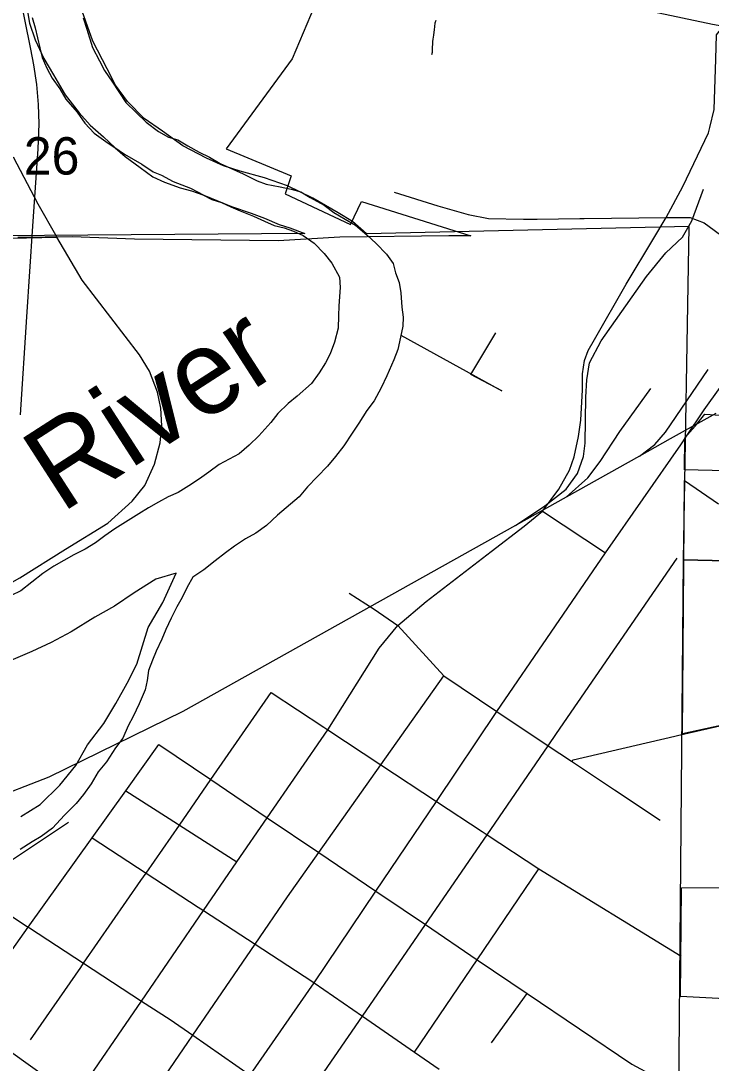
# Model space of a CAD drawing. Extents: x -8.5 to 18.7, y -20.3 to 7.
# Drawn here: x -4.269 to -2.724, y 1.955 to 4.29 of the extents above; entities that cross this region are included whole.
import ezdxf

# ---------------------------------------------------------------- set-up
doc = ezdxf.new("R2010")
doc.units = 0
for name, color, linetype in [('GM_X_City_Street', 7, 'Continuous'), ('GM_X_County_Road', 7, 'Continuous'), ('GM_X_Major_River', 7, 'Continuous'), ('GM_X_Major_River_Text', 7, 'Continuous'), ('GM_X_Minor_River', 7, 'Continuous'), ('GM_X_Rail_Line', 7, 'Continuous'), ('GM_X_Section', 7, 'Continuous'), ('GM_X_Section_Text', 7, 'Continuous'), ('GM_X_Township_Road', 7, 'Continuous')]:
    doc.layers.add(name, color=color, linetype=linetype)

msp = doc.modelspace()

# ---------------------------------------------------------------- linework, layer by layer
at = {"layer": 'GM_X_City_Street'}
for p, q in [((-3.1135, 3.8456), (-3.0178, 3.8468)), ((-3.1012, 3.1917), (-2.9599, 3.0981)), ((-4.0345, 2.5653), (-3.9182, 2.4909)), ((-3.2152, 2.0004), (-3.1355, 2.111))]:
    msp.add_line(p, q, dxfattribs=at)
for points in [[(-3.5552, 4.4573), (-3.6617, 4.2047), (-3.8097, 4.0028), (-3.6637, 3.9428), (-3.6775, 3.9025), (-3.5312, 3.8333), (-3.5068, 3.8847), (-3.2619, 3.8083), (-3.3107, 3.8078), (-3.5552, 3.8048), (-3.6928, 3.7972), (-4.0146, 3.8004), (-4.1541, 3.8061), (-4.2764, 3.8042)], [(-2.2079, 4.2918), (-2.2137, 4.1138), (-2.3043, 4.1716), (-2.4194, 4.2152), (-2.5061, 4.2422), (-2.6097, 4.2619), (-2.7206, 4.2815), (-3.5022, 4.4472)], [(-3.4331, 3.9059), (-3.3358, 3.8751), (-3.2679, 3.8558), (-3.2219, 3.8466), (-3.1441, 3.8452), (-3.1135, 3.8456)], [(-3.4249, 2.9356), (-3.3618, 2.9894), (-3.2164, 3.1009), (-3.142, 3.1578), (-3.1012, 3.1917), (-3.0649, 3.2408), (-3.0409, 3.2833), (-3.0302, 3.3131), (-3.021, 3.3584), (-3.0155, 3.3954), (-3.0114, 3.4633), (-3.0114, 3.4993), (-3.0076, 3.5292), (-2.999, 3.5514), (-2.985, 3.5761), (-2.914, 3.6995), (-2.8523, 3.803), (-2.8242, 3.8493)], [(-3.0178, 3.8468), (-3.0083, 3.8469), (-2.8242, 3.8493)], [(-2.8242, 3.8493), (-2.771, 3.8493), (-2.7391, 3.8373), (-2.5845, 3.7238)], [(-4.855, 2.6195), (-4.7618, 2.6604), (-4.7141, 2.6911), (-4.6291, 2.7728), (-4.4997, 2.9022), (-4.3942, 2.9737), (-4.2717, 3.0418), (-4.1696, 3.1065), (-4.0744, 3.1643), (-4.0203, 3.2136), (-3.9919, 3.249), (-3.9698, 3.2969), (-3.9571, 3.3442), (-3.9535, 3.3827), (-3.9557, 3.4219), (-3.9632, 3.458), (-3.9812, 3.5046), (-4.0037, 3.5412), (-4.1324, 3.709), (-4.189, 3.8052)], [(-2.5677, 3.2786), (-2.7832, 3.2842), (-2.7825, 3.3554), (-2.7596, 3.3817), (-2.7381, 3.4083), (-2.7026, 3.4067)], [(-2.7021, 2.7117), (-2.7882, 2.6929), (-2.7834, 3.2602), (-2.7075, 3.208)], [(-3.6846, 1.7981), (-3.6473, 1.8524), (-3.5983, 1.9238), (-3.5046, 2.0602), (-3.3636, 2.2654), (-3.2254, 2.4668), (-3.0885, 2.666), (-3.0696, 2.6935), (-2.7999, 3.0863)], [(-3.5343, 3.0076), (-3.4784, 2.9719), (-3.4249, 2.9356)], [(-4.0651, 1.7538), (-3.8957, 2.0013), (-3.8846, 2.0175), (-3.7449, 2.2214), (-3.672, 2.3279), (-3.6021, 2.4267), (-3.4631, 2.6233), (-3.3221, 2.8227)], [(-4.2474, 2.0074), (-4.1352, 2.1694), (-4.1287, 2.179), (-4.0006, 2.3639), (-3.9889, 2.3809), (-3.9144, 2.4884), (-3.844, 2.5902), (-3.7089, 2.7853)], [(-3.7089, 2.7853), (-3.5908, 2.7075), (-3.5823, 2.7018), (-3.4631, 2.6233), (-3.3389, 2.5415), (-3.2364, 2.474)], [(-4.4625, 1.9578), (-4.3961, 2.055), (-4.3292, 2.1531), (-4.2528, 2.26), (-4.1098, 2.4599), (-4.0345, 2.5653), (-3.9604, 2.6689)], [(-3.9604, 2.6689), (-3.844, 2.5902), (-3.7175, 2.5047), (-3.6021, 2.4267), (-3.4745, 2.3404), (-3.4132, 2.299), (-3.3636, 2.2654), (-3.2476, 2.1868), (-3.1355, 2.111), (-2.9015, 1.9525), (-2.8514, 1.926), (-2.7975, 1.8934), (-2.779, 1.8934), (-2.7151, 1.9279)], [(-3.0367, 2.6314), (-2.9401, 2.5673), (-2.8378, 2.4994)], [(-4.3286, 2.3757), (-4.308, 2.398), (-4.1625, 2.495)], [(-3.9182, 2.4909), (-3.9144, 2.4884), (-3.7854, 2.4058)], [(-4.1098, 2.4599), (-3.9889, 2.3809), (-3.8724, 2.3048), (-3.8601, 2.2968), (-3.7449, 2.2214), (-3.618, 2.1385), (-3.6129, 2.1352)], [(-3.2364, 2.474), (-3.2254, 2.4668), (-3.1098, 2.3907), (-2.791, 2.195)], [(-3.3878, 1.9794), (-3.2476, 2.1868), (-3.1098, 2.3907)], [(-4.3667, 2.3345), (-4.2528, 2.26), (-4.2496, 2.258)], [(-2.2535, 2.0761), (-2.7923, 2.1042), (-2.79, 2.3481), (-2.595, 2.3486)], [(-4.2496, 2.258), (-4.1287, 2.179), (-3.999, 2.0943), (-3.9351, 2.0526), (-3.8846, 2.0175), (-3.756, 1.928), (-3.6473, 1.8524), (-3.6362, 1.8446), (-3.5475, 1.7829), (-3.4907, 1.7508), (-3.4206, 1.7225), (-3.4109, 1.7186), (-3.2809, 1.6661), (-3.1664, 1.6197), (-3.0423, 1.5696), (-2.9414, 1.5288), (-2.937, 1.5266), (-2.8785, 1.4971), (-2.7977, 1.4775)], [(-4.6059, 2.2049), (-4.5241, 2.1464), (-4.5198, 2.1433), (-4.3961, 2.055), (-4.3932, 2.0529), (-4.1477, 1.8776)]]:
    msp.add_lwpolyline(points, dxfattribs=at)
at = {"layer": 'GM_X_County_Road'}
msp.add_line((-2.7773, 3.3618), (-2.7436, 3.4117), dxfattribs=at)
for points in [[(-2.8242, 3.8493), (-2.7874, 3.9185), (-2.7297, 4.0387), (-2.7267, 4.0507), (-2.7167, 4.0909), (-2.7135, 4.2041), (-2.7119, 4.2584), (-2.6997, 4.2732)], [(-2.7436, 3.4117), (-2.7391, 3.4184), (-2.7036, 3.4685), (-2.6743, 3.5046), (-2.6518, 3.5266), (-2.6057, 3.5626), (-2.5098, 3.6339)], [(-3.2033, 2.7427), (-2.9599, 3.0981), (-2.7919, 3.3402), (-2.7773, 3.3618)], [(-4.2006, 1.7945), (-4.197, 1.8032), (-4.1944, 1.8094), (-4.1477, 1.8776), (-3.999, 2.0943), (-3.8601, 2.2968), (-3.7854, 2.4058), (-3.7175, 2.5047), (-3.5823, 2.7018), (-3.4667, 2.8848), (-3.4249, 2.9356)], [(-3.4249, 2.9356), (-3.3221, 2.8227), (-3.2033, 2.7427)], [(-3.7548, 1.9296), (-3.6129, 2.1352), (-3.4745, 2.3404), (-3.3389, 2.5415), (-3.2033, 2.7427)], [(-3.2033, 2.7427), (-3.0885, 2.666), (-3.0367, 2.6314), (-3.0345, 2.6328)], [(-2.7988, 2.6888), (-2.688, 2.7147), (-2.6802, 2.7165)], [(-3.0345, 2.6328), (-3.0324, 2.6342), (-2.8047, 2.6874), (-2.7988, 2.6888)], [(-3.6129, 2.1352), (-3.5046, 2.0602), (-3.3878, 1.9794), (-3.333, 1.9415)]]:
    msp.add_lwpolyline(points, dxfattribs=at)
at = {"layer": 'GM_X_Major_River'}
for points in [[(-4.2438, 4.2971), (-4.2372, 4.2742), (-4.2322, 4.2514), (-4.2271, 4.2293), (-4.2213, 4.2073), (-4.2109, 4.1836), (-4.1991, 4.1615), (-4.1819, 4.137), (-4.1685, 4.1141), (-4.143, 4.085), (-4.1259, 4.0605), (-4.1049, 4.0382)], [(-4.13, 4.2966), (-4.1219, 4.2707), (-4.1088, 4.2296), (-4.0932, 4.1998), (-4.082, 4.1784), (-4.0641, 4.1524), (-4.0343, 4.1066), (-4.011, 4.0843), (-3.9885, 4.0628), (-3.9614, 4.042), (-3.9388, 4.0289), (-3.9176, 4.0233)], [(-4.1049, 4.0382), (-4.0793, 4.0197), (-4.0582, 4.0051), (-4.0357, 3.9859), (-4.0018, 3.9612), (-3.974, 3.9404), (-3.9476, 3.928), (-3.9128, 3.9155), (-3.8871, 3.9091), (-3.8621, 3.8997), (-3.8418, 3.8896), (-3.8199, 3.8826), (-3.7995, 3.8733), (-3.7783, 3.8639), (-3.7481, 3.8522), (-3.724, 3.8406), (-3.7021, 3.8312), (-3.6794, 3.8257), (-3.659, 3.8186), (-3.6371, 3.8085), (-3.6123, 3.7915), (-3.5898, 3.7685), (-3.5733, 3.7471), (-3.5562, 3.7158), (-3.5542, 3.6922), (-3.5577, 3.6513), (-3.558, 3.6292), (-3.559, 3.6012), (-3.567, 3.5701), (-3.5764, 3.5436), (-3.5872, 3.5233), (-3.6011, 3.5014), (-3.6189, 3.4773), (-3.6503, 3.4488), (-3.671, 3.4323), (-3.694, 3.4105), (-3.7094, 3.3902), (-3.7363, 3.3601), (-3.7578, 3.3391), (-3.7807, 3.3196), (-3.825, 3.2957), (-3.8487, 3.2785), (-3.8694, 3.2636), (-3.8931, 3.2479), (-3.9168, 3.2329), (-3.9396, 3.2233), (-3.961, 3.2114), (-3.9832, 3.1987), (-4.0053, 3.1853), (-4.029, 3.1704), (-4.0588, 3.1517), (-4.081, 3.136), (-4.1024, 3.1203), (-4.1253, 3.1061), (-4.1505, 3.0935), (-4.1734, 3.0808), (-4.1955, 3.0681), (-4.22, 3.0517), (-4.269, 3.0127), (-4.2911, 3.0023)], [(-3.9176, 4.0233), (-3.8958, 4.0094), (-3.8702, 3.9955), (-3.8468, 3.9846), (-3.8227, 3.9699), (-3.7713, 3.9466), (-3.7404, 3.9311), (-3.72, 3.924), (-3.689, 3.9176), (-3.664, 3.9128), (-3.6421, 3.9065), (-3.6217, 3.8941), (-3.59, 3.8771), (-3.5682, 3.8602), (-3.5434, 3.8455), (-3.52, 3.8316), (-3.4937, 3.8093), (-3.4734, 3.7908), (-3.4509, 3.767), (-3.436, 3.7464), (-3.4302, 3.7251), (-3.4221, 3.7037), (-3.4185, 3.6801), (-3.4166, 3.6482), (-3.4131, 3.6262), (-3.4141, 3.6057), (-3.4189, 3.5814), (-3.4253, 3.5534), (-3.4339, 3.53), (-3.4495, 3.4945), (-3.4627, 3.468), (-3.4782, 3.4386), (-3.4944, 3.4167), (-3.5129, 3.3888), (-3.5276, 3.3662), (-3.5461, 3.3376), (-3.5646, 3.3135), (-3.583, 3.2924), (-3.6061, 3.2684), (-3.6276, 3.2458), (-3.646, 3.2232), (-3.6943, 3.1827), (-3.7196, 3.1595), (-3.7433, 3.1423), (-3.7662, 3.1296), (-3.7907, 3.1132), (-3.8113, 3.0982), (-3.8343, 3.0802), (-3.8596, 3.06), (-3.884, 3.0436), (-3.8972, 3.0209), (-3.908, 2.9983), (-3.9204, 2.9771), (-3.9329, 2.9514), (-3.9445, 2.9265), (-3.9539, 2.9046), (-3.9663, 2.8782), (-3.9749, 2.8577), (-3.9835, 2.8343), (-3.9868, 2.8123), (-3.9908, 2.7911), (-4.0041, 2.7601), (-4.0181, 2.7314), (-4.0289, 2.7103), (-4.0406, 2.6831), (-4.0575, 2.6612), (-4.0776, 2.6303), (-4.0961, 2.6077), (-4.1116, 2.5806), (-4.1293, 2.5572), (-4.1454, 2.5369), (-4.1715, 2.5106), (-4.1984, 2.4813), (-4.2237, 2.4626), (-4.2443, 2.4506), (-4.271, 2.4335)], [(-3.9219, 3.0523), (-3.9668, 3.0391), (-4.0157, 3.0085), (-4.06, 2.9786), (-4.1035, 2.954), (-4.157, 2.9212), (-4.2013, 2.8974), (-4.2448, 2.8773), (-4.292, 2.8573)], [(-4.0099, 2.849), (-3.9845, 2.9308), (-3.9513, 2.9872), (-3.9219, 3.0523)], [(-4.2694, 2.5078), (-4.2259, 2.5347), (-4.1822, 2.5775), (-4.146, 2.6219), (-4.1204, 2.668), (-4.0835, 2.7162), (-4.0564, 2.7607), (-4.0316, 2.806), (-4.0099, 2.849)]]:
    msp.add_lwpolyline(points, dxfattribs=at)
at = {"layer": 'GM_X_Minor_River'}
for p, q in [((-3.4184, 3.5855), (-3.1925, 3.4607)), ((-3.2614, 3.4977), (-3.2057, 3.5907)), ((-3.1925, 3.4607), (-3.2614, 3.4977))]:
    msp.add_line(p, q, dxfattribs=at)
msp.add_lwpolyline([(-3.3403, 4.2906), (-3.3427, 4.2846), (-3.3429, 4.277), (-3.3438, 4.2694), (-3.3446, 4.2641), (-3.3455, 4.2573), (-3.3465, 4.2482), (-3.3474, 4.243), (-3.3475, 4.2369), (-3.3483, 4.2316), (-3.3486, 4.2187), (-3.3495, 4.2134)], dxfattribs=at)
at = {"layer": 'GM_X_Rail_Line'}
for p, q in [((-2.8842, 3.3146), (-3.048, 3.223)), ((-3.048, 3.223), (-3.1615, 3.1595))]:
    msp.add_line(p, q, dxfattribs=at)
for points in [[(-4.2736, 4.3564), (-4.2479, 4.226), (-4.241, 4.1908), (-4.2346, 4.1472), (-4.2304, 4.1025), (-4.2293, 4.0591), (-4.2312, 4.0032), (-4.2429, 3.8296), (-4.2566, 3.6268), (-4.271, 3.407)], [(-3.1615, 3.1595), (-3.0963, 3.2032), (-3.0485, 3.2409), (-3.0226, 3.2757), (-3.0095, 3.3135), (-3.0058, 3.344), (-3.0042, 3.4465), (-3.0024, 3.4854), (-2.9962, 3.5233), (-2.9702, 3.5729), (-2.8683, 3.7171), (-2.8255, 3.77), (-2.7881, 3.8053), (-2.7671, 3.8416), (-2.7409, 3.9129)], [(-2.8842, 3.3146), (-2.8495, 3.3405), (-2.8259, 3.3684), (-2.73, 3.5088)], [(-3.048, 3.223), (-2.9999, 3.2657), (-2.9725, 3.3024), (-2.9285, 3.3701), (-2.8591, 3.4658)], [(-2.7131, 3.4098), (-2.8153, 3.3532), (-2.8842, 3.3146)], [(-3.1615, 3.1595), (-3.9064, 2.7429), (-4.2069, 2.5956), (-4.3455, 2.5417)]]:
    msp.add_lwpolyline(points, dxfattribs=at)
at = {"layer": 'GM_X_Section'}
for points in [[(-2.2011, 5.074), (-2.2369, 3.07), (-2.7857, 3.0825), (-2.7727, 3.829), (-3.4952, 3.8123), (-3.5269, 3.8405), (-3.5586, 3.8596), (-3.6152, 3.8926), (-3.6719, 3.9202), (-3.7241, 3.938), (-3.7779, 3.9527), (-3.8157, 3.9651), (-3.8535, 3.982), (-3.9064, 4.0096), (-3.9524, 4.0425), (-3.9932, 4.0708), (-4.0308, 4.1089), (-4.0571, 4.1454), (-4.0759, 4.1819), (-4.1081, 4.2443), (-4.1394, 4.3324)], [(-4.2584, 4.3324), (-4.2496, 4.2846), (-4.2369, 4.2474), (-4.2175, 4.2056), (-4.1965, 4.1683), (-4.1702, 4.1242), (-4.1386, 4.0838), (-4.1138, 4.0556), (-4.0844, 4.0296), (-4.0587, 4.006), (-4.0369, 3.9907), (-3.9983, 3.9685), (-3.9734, 3.9516), (-3.9545, 3.9439), (-3.9281, 3.9294), (-3.8895, 3.9147), (-3.8593, 3.8994), (-3.7973, 3.874), (-3.7534, 3.8586), (-3.7239, 3.8478), (-3.6907, 3.8332), (-3.6672, 3.8262), (-3.6332, 3.8131), (-4.3131, 3.8082)]]:
    msp.add_lwpolyline(points, dxfattribs=at)
msp.add_lwpolyline([(-2.2369, 3.07), (-2.2915, 1.1056), (-2.4613, 1.1112), (-2.8031, 1.1178), (-2.7857, 3.0825)], close=True, dxfattribs=at)
at = {"layer": 'GM_X_Township_Road'}
msp.add_line((-4.2903, 3.8025), (-4.189, 3.8052), dxfattribs=at)
msp.add_lwpolyline([(-4.2864, 3.9849), (-4.2311, 3.8796), (-4.189, 3.8052)], dxfattribs=at)

# ---------------------------------------------------------------- texts
at = {"layer": 'GM_X_Major_River_Text'}
msp.add_text('River', height=0.1895, rotation=32.8257, dxfattribs=at).set_placement((-4.1788, 3.1854))
at = {"layer": 'GM_X_Section_Text'}
msp.add_text('26', height=0.08371, rotation=0, dxfattribs=at).set_placement((-4.2627, 3.9453))

doc.saveas('drawing.dxf')
